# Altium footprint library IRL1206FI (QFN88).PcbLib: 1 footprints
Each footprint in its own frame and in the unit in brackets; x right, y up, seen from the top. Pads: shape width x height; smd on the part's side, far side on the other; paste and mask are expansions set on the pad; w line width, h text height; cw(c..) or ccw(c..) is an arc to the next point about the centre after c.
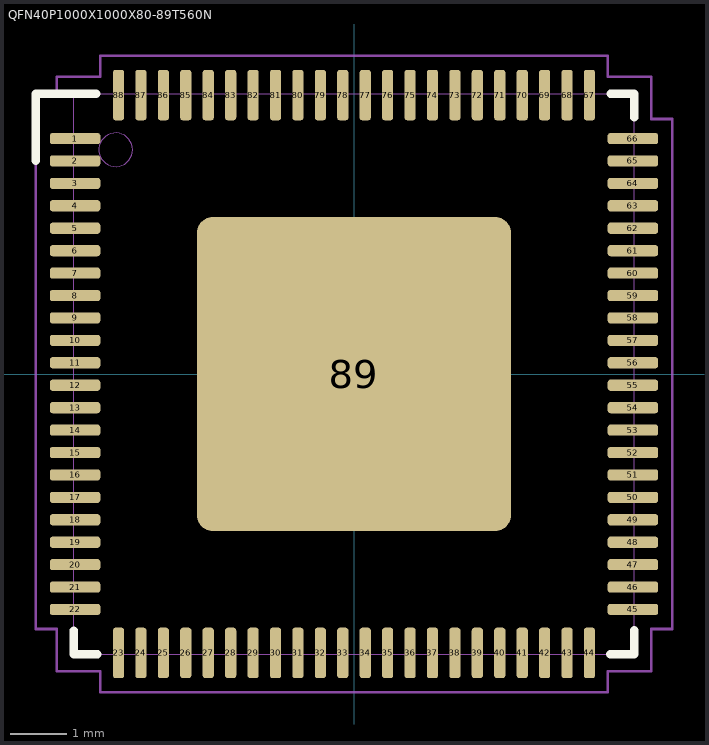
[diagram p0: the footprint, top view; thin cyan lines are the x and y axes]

## QFN40P1000X1000X80-89T560N [mm] "88-QFN, 0.40 mm pitch, 10.00 X 10.00 X 0.80 mm body, 5.60 X 5.60 mm thermal pad"
height 0.8
pads (89):
  rrect50% 0.9x0.2 smd mask+0.05: 1(-4.975,4.2) 2(-4.975,3.8) 3(-4.975,3.4) 4(-4.975,3) 5(-4.975,2.6) 6(-4.975,2.2) 7(-4.975,1.8) 8(-4.975,1.4) 9(-4.975,1) 10(-4.975,0.6) 11(-4.975,0.2) 12(-4.975,-0.2) 13(-4.975,-0.6) 14(-4.975,-1) 15(-4.975,-1.4) 16(-4.975,-1.8) 17(-4.975,-2.2) 18(-4.975,-2.6) 19(-4.975,-3) 20(-4.975,-3.4) 21(-4.975,-3.8) 22(-4.975,-4.2) 45(4.975,-4.2) 46(4.975,-3.8) 47(4.975,-3.4) 48(4.975,-3) 49(4.975,-2.6) 50(4.975,-2.2) 51(4.975,-1.8) 52(4.975,-1.4) 53(4.975,-1) 54(4.975,-0.6) 55(4.975,-0.2) 56(4.975,0.2) 57(4.975,0.6) 58(4.975,1) 59(4.975,1.4) 60(4.975,1.8) 61(4.975,2.2) 62(4.975,2.6) 63(4.975,3) 64(4.975,3.4) 65(4.975,3.8) 66(4.975,4.2)
  rrect50% 0.2x0.9 smd mask+0.05: 23(-4.2,-4.975) 24(-3.8,-4.975) 25(-3.4,-4.975) 26(-3,-4.975) 27(-2.6,-4.975) 28(-2.2,-4.975) 29(-1.8,-4.975) 30(-1.4,-4.975) 31(-1,-4.975) 32(-0.6,-4.975) 33(-0.2,-4.975) 34(0.2,-4.975) 35(0.6,-4.975) 36(1,-4.975) 37(1.4,-4.975) 38(1.8,-4.975) 39(2.2,-4.975) 40(2.6,-4.975) 41(3,-4.975) 42(3.4,-4.975) 43(3.8,-4.975) 44(4.2,-4.975) 67(4.2,4.975) 68(3.8,4.975) 69(3.4,4.975) 70(3,4.975) 71(2.6,4.975) 72(2.2,4.975) 73(1.8,4.975) 74(1.4,4.975) 75(1,4.975) 76(0.6,4.975) 77(0.2,4.975) 78(-0.2,4.975) 79(-0.6,4.975) 80(-1,4.975) 81(-1.4,4.975) 82(-1.8,4.975) 83(-2.2,4.975) 84(-2.6,4.975) 85(-3,4.975) 86(-3.4,4.975) 87(-3.8,4.975) 88(-4.2,4.975)
  rrect10% 5.6x5.6 smd paste-2539.97 mask+0.05: 89(0,0)
Top Overlay:
  lines w0.15: -5.674,3.8 -5.674,5 -4.6,5 ; -5,-4.575 -5,-5 -4.575,-5 ; 4.574,-4.999 4.999,-4.999 4.999,-4.574 ; 4.575,5 5,5 5,4.575
Top Paste:
  drawing of 144 lines, arcs and shapes, not listed
Top Assembly:
  circle w0: c-4.25,4 r0.3
  lines w0: -5,-5 -5,5 5,5 5,-5 -5,-5
  text ".Designator" at -2.618,-0.355 h1.52
Top Courtyard:
  lines w0.05: -5.675,-4.55 -5.675,5 -5.3,5 -5.3,5.3 -4.525,5.3 -4.525,5.675 4.525,5.675 4.525,5.3 5.3,5.3 5.3,4.55 5.675,4.55 5.675,-4.55 5.3,-4.55 5.3,-5.3 4.525,-5.3 4.525,-5.675 -4.525,-5.675 -4.525,-5.3 -5.3,-5.3 -5.3,-4.55 -5.675,-4.55
3D body "QFN40P1000X1000X80-89T560.STEP": height 0.8, standoff 0, extent -5.001,-5.001 5.001,5.001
